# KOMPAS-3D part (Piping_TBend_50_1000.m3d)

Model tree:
1. Plane XY
2. Plane ZX
3. Plane ZY
4. X Axis
5. Y Axis
6. Z Axis
7. Origin
8. Sketch:1
9. Extrude:2  (labels: На расстояние 1; На расстояние 2)
     Толщина стенки 1 = 1; Толщина стенки 2 = 1
10. Sketch:3
11. Extrude:3  (labels: На расстояние 1; На расстояние 2)
     Толщина стенки 1 = 1; Толщина стенки 2 = 1; Расстояние 2 = 14
12. Sketch:4
13. Cut-Extrude:1  (labels: На расстояние 1; На расстояние 2)
     Толщина стенки 1 = 1; Толщина стенки 2 = 1; Расстояние 1 = 64; Расстояние 2 = 64
14. Sketch:6
15. Cut-Extrude:3  (labels: На расстояние 1; На расстояние 2)
     Толщина стенки 1 = 1; Толщина стенки 2 = 1; Расстояние 1 = 64; Расстояние 2 = 5.0494
16. Control point:1
17. Sketch:7
18. Attachment Point:1
19. Sketch:8
20. Attachment Point:2
21. Sketch:9
22. Attachment Point:3

Expressions: D-2*T; D1-2*T1
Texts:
  T-bend Dn 50
  Steel ASTM A295
  Three Point Plane
  Plane at Angle
  Line and Point Plane
  Axis through Two Vertices
  Axis of Feature
  Axis of Conical Surface
  Axis through Edge
  Приклеить элемент выдавливания
  Приклеить элемент вращения
  Приклеить кинематический элемент
  Приклеить элемент по сечениям
  Trim by Surface
  Trim by Sketch
  Feature with No History
  Intersection Axis of Two Planes
  Two Line Plane
  Line and Face Plane
  Bend by line
  Hole in sheet body
  Cut in sheet body
  Point in CM
  Linear Dimension from Line to Point
  Surface Finish Symbol
  Geometric Tolerance Symbol
  Текст на чертеже
  Линия-выноска #1
  Линия-выноска #2
  Линия-выноска #3
  Отклонения формы и база
  Марка координационной оси
  Марка/позиционное обозначение с линией-выноской
  Марка/позиционное обозначение на линии
  Марка/позиционное обозначение без линии-выноски
  Марки/позиционные обозначения с линией-выноской
  Марки/позиционные обозначения на линии
  Марки/позиционные обозначения без линии-выноски
  На расстояние 1
  На расстояние 2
